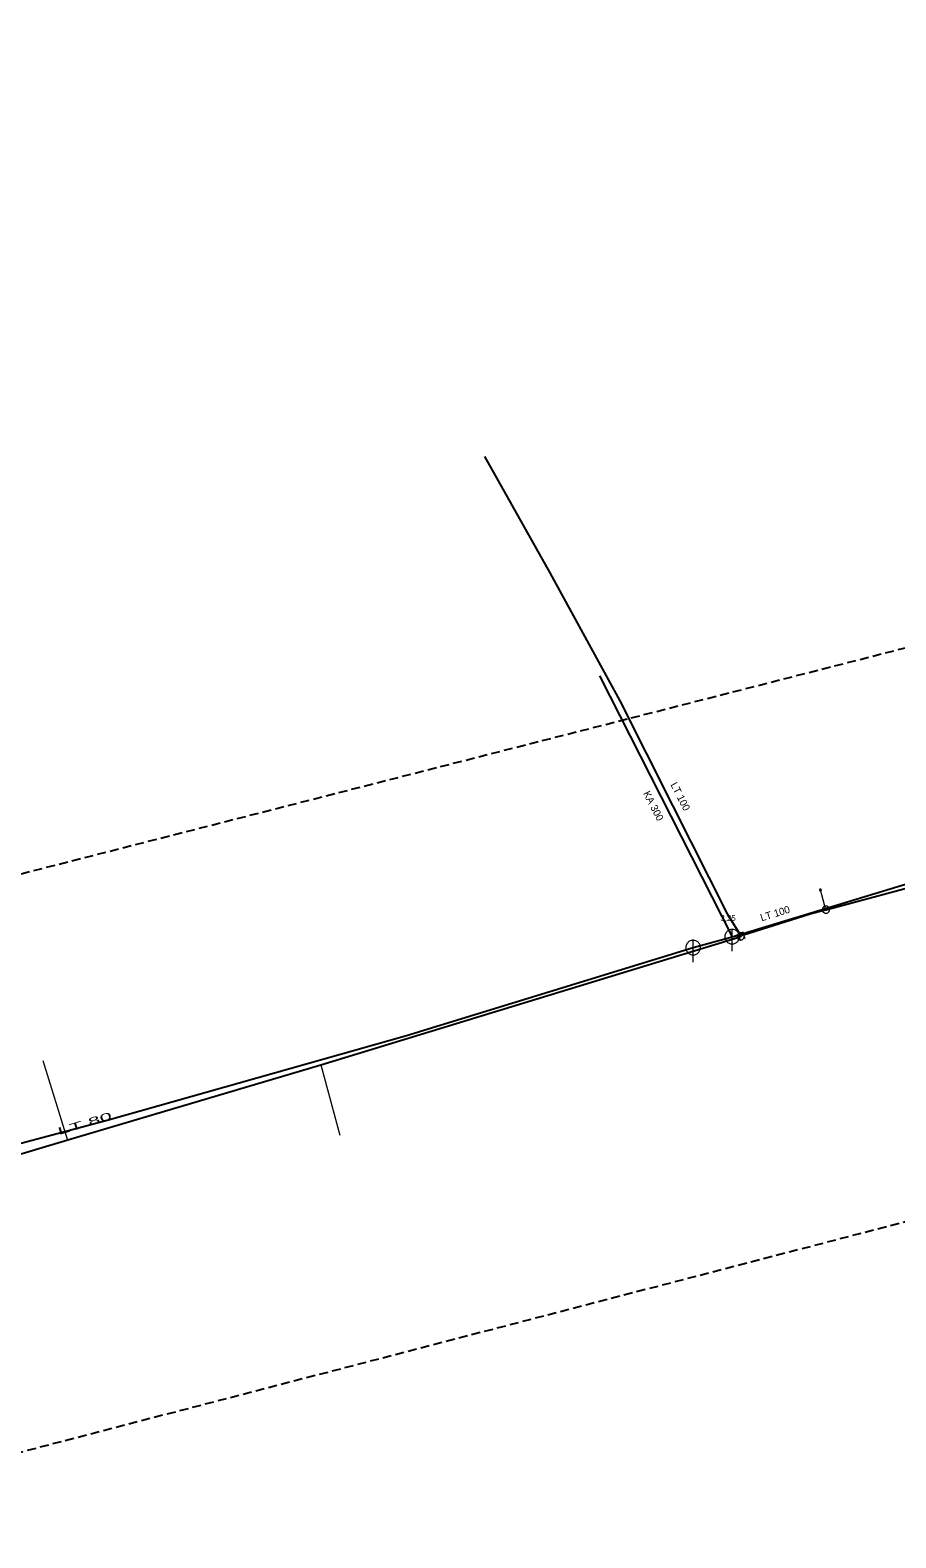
# Model space of a CAD drawing. Extents: x -690254 to -689100, y -975264 to -974703.
# Drawn here: x -689579.1 to -689460.4, y -974970.5 to -974763.7 of the extents above; entities that cross this region are included whole.
import ezdxf

# ---------------------------------------------------------------- set-up
doc = ezdxf.new("R2010")
doc.units = 0
doc.header["$LTSCALE"] = 0.4
doc.linetypes.add('MEDIUM_DASHED', pattern=[4.5, 3, -1.5])
for name, color, linetype, lineweight in [('1', 7, 'Continuous', 13), ('13', 7, 'Continuous', 13), ('14', 7, 'Continuous', 13), ('17', 7, 'Continuous', 25), ('22', 7, 'Continuous', 13), ('34', 7, 'Continuous', 13), ('47', 7, 'Continuous', 13), ('63', 7, 'MEDIUM_DASHED', 25), ('9', 7, 'Continuous', 13)]:
    doc.layers.add(name, color=color, linetype=linetype, lineweight=lineweight)

msp = doc.modelspace()

# ---------------------------------------------------------------- linework, layer by layer
at = {"layer": '13'}
for p, q in [((-689573.992, -974915.884), (-689577.329, -974905.072)), ((-689539.272, -974905.616), (-689536.647, -974915.287))]:
    msp.add_line(p, q, dxfattribs=at)
at = {"layer": '14', "lineweight": 25}
msp.add_line((-689501.039, -974852.239), (-689482.829, -974888.039), dxfattribs=at)
at = {"layer": '14'}
for p, q in [((-689469.955, -974884.335), (-689470.711, -974881.63)), ((-689573.976, -974915.931), (-689573.992, -974915.884))]:
    msp.add_line(p, q, dxfattribs=at)
at = {"layer": '14', "lineweight": 25}
for points in [[(-689488.181, -974889.533), (-689482.829, -974888.039), (-689415.219, -974867.53)], [(-689624.679, -974928.186), (-689568.576, -974913.204), (-689527.509, -974901.581), (-689488.181, -974889.533)]]:
    msp.add_lwpolyline(points, dxfattribs=at)
at = {"layer": '14'}
msp.add_lwpolyline([(-689481.914, -974888.101), (-689481.66, -974888), (-689481.25, -974887.809)], dxfattribs=at)
at = {"layer": '17'}
for points in [[(-689516.78, -974822.14), (-689507.85, -974838.14), (-689498.219, -974855.68), (-689491, -974870.039), (-689483.487, -974884.918), (-689481.92, -974887.48), (-689481.66, -974888)], [(-689469.955, -974884.335), (-689442.62, -974876.987), (-689427.163, -974872.924), (-689420.942, -974870.852), (-689400.344, -974864.98), (-689376.509, -974858.111), (-689369.914, -974856.032), (-689358.632, -974852.602)], [(-689481.25, -974887.809), (-689472.099, -974884.916), (-689469.955, -974884.335)], [(-689605.756, -974925.377), (-689599.249, -974923.443), (-689573.976, -974915.931), (-689539.272, -974905.616), (-689481.914, -974888.101)]]:
    msp.add_lwpolyline(points, dxfattribs=at)
at = {"layer": '22'}
for p, q in [((-689482.829, -974890.039), (-689482.828, -974887.039)), ((-689488.181, -974891.533), (-689488.18, -974888.533))]:
    msp.add_line(p, q, dxfattribs=at)
for points in [[(-689481.829, -974888.039), (-689481.834, -974887.93), (-689481.852, -974887.822), (-689481.882, -974887.716), (-689481.922, -974887.615), (-689481.974, -974887.518), (-689482.036, -974887.428), (-689482.108, -974887.345), (-689482.188, -974887.271), (-689482.276, -974887.205), (-689482.37, -974887.15), (-689482.47, -974887.105), (-689482.575, -974887.072), (-689482.682, -974887.05), (-689482.791, -974887.04), (-689482.901, -974887.042), (-689483.009, -974887.056), (-689483.116, -974887.081), (-689483.219, -974887.118), (-689483.317, -974887.167), (-689483.409, -974887.225), (-689483.495, -974887.294), (-689483.572, -974887.371), (-689483.641, -974887.457), (-689483.7, -974887.549), (-689483.748, -974887.647), (-689483.785, -974887.75), (-689483.811, -974887.857), (-689483.825, -974887.965), (-689483.828, -974888.075), (-689483.818, -974888.184), (-689483.797, -974888.291), (-689483.763, -974888.395), (-689483.719, -974888.495), (-689483.664, -974888.59), (-689483.598, -974888.678), (-689483.524, -974888.758), (-689483.441, -974888.83), (-689483.351, -974888.892), (-689483.255, -974888.944), (-689483.153, -974888.985), (-689483.048, -974889.015), (-689482.94, -974889.033), (-689482.83, -974889.039), (-689482.721, -974889.033), (-689482.613, -974889.015), (-689482.508, -974888.986), (-689482.406, -974888.945), (-689482.309, -974888.893), (-689482.219, -974888.831), (-689482.136, -974888.76), (-689482.061, -974888.68), (-689481.996, -974888.592), (-689481.94, -974888.498), (-689481.896, -974888.398), (-689481.862, -974888.294), (-689481.84, -974888.186), (-689481.83, -974888.077)], [(-689487.181, -974889.533), (-689487.186, -974889.424), (-689487.204, -974889.316), (-689487.234, -974889.21), (-689487.274, -974889.109), (-689487.326, -974889.012), (-689487.388, -974888.922), (-689487.46, -974888.839), (-689487.54, -974888.765), (-689487.628, -974888.699), (-689487.722, -974888.644), (-689487.822, -974888.599), (-689487.927, -974888.566), (-689488.034, -974888.544), (-689488.143, -974888.534), (-689488.253, -974888.536), (-689488.361, -974888.55), (-689488.468, -974888.575), (-689488.571, -974888.612), (-689488.669, -974888.661), (-689488.761, -974888.719), (-689488.847, -974888.788), (-689488.924, -974888.865), (-689488.993, -974888.951), (-689489.052, -974889.043), (-689489.1, -974889.141), (-689489.137, -974889.244), (-689489.163, -974889.351), (-689489.177, -974889.459), (-689489.18, -974889.569), (-689489.17, -974889.678), (-689489.149, -974889.785), (-689489.115, -974889.889), (-689489.071, -974889.989), (-689489.016, -974890.084), (-689488.95, -974890.172), (-689488.876, -974890.252), (-689488.793, -974890.324), (-689488.703, -974890.386), (-689488.607, -974890.438), (-689488.505, -974890.479), (-689488.4, -974890.509), (-689488.292, -974890.527), (-689488.182, -974890.533), (-689488.073, -974890.527), (-689487.965, -974890.509), (-689487.86, -974890.48), (-689487.758, -974890.439), (-689487.661, -974890.387), (-689487.571, -974890.325), (-689487.488, -974890.254), (-689487.413, -974890.174), (-689487.348, -974890.086), (-689487.292, -974889.992), (-689487.248, -974889.892), (-689487.214, -974889.788), (-689487.192, -974889.68), (-689487.182, -974889.571)]]:
    msp.add_lwpolyline(points, close=True, dxfattribs=at)
at = {"layer": '34'}
for p, q in [((-689481.401, -974887.332), (-689481.099, -974888.285)), ((-689482.156, -974887.663), (-689481.672, -974888.538)), ((-689574.465, -974916.045), (-689573.518, -974915.723))]:
    msp.add_line(p, q, dxfattribs=at)
at = {"layer": '47'}
for points in [[(-689469.474, -974884.197), (-689469.491, -974884.148), (-689469.513, -974884.1), (-689469.54, -974884.056), (-689469.571, -974884.014), (-689469.607, -974883.975), (-689469.647, -974883.941), (-689469.689, -974883.911), (-689469.735, -974883.886), (-689469.783, -974883.865), (-689469.833, -974883.849), (-689469.885, -974883.839), (-689469.937, -974883.835), (-689469.989, -974883.836), (-689470.041, -974883.842), (-689470.092, -974883.854), (-689470.141, -974883.871), (-689470.189, -974883.893), (-689470.234, -974883.92), (-689470.275, -974883.951), (-689470.314, -974883.987), (-689470.348, -974884.027), (-689470.378, -974884.07), (-689470.404, -974884.115), (-689470.425, -974884.163), (-689470.44, -974884.213), (-689470.45, -974884.265), (-689470.454, -974884.317), (-689470.453, -974884.369), (-689470.447, -974884.421), (-689470.435, -974884.472), (-689470.418, -974884.521), (-689470.396, -974884.569), (-689470.37, -974884.614), (-689470.338, -974884.655), (-689470.302, -974884.694), (-689470.263, -974884.728), (-689470.22, -974884.759), (-689470.174, -974884.784), (-689470.126, -974884.805), (-689470.076, -974884.82), (-689470.024, -974884.83), (-689469.973, -974884.835), (-689469.92, -974884.833), (-689469.868, -974884.827), (-689469.817, -974884.815), (-689469.768, -974884.798), (-689469.72, -974884.776), (-689469.676, -974884.75), (-689469.634, -974884.718), (-689469.595, -974884.682), (-689469.561, -974884.643), (-689469.531, -974884.6), (-689469.506, -974884.555), (-689469.485, -974884.506), (-689469.469, -974884.456), (-689469.459, -974884.404), (-689469.455, -974884.353), (-689469.456, -974884.3), (-689469.462, -974884.248)], [(-689469.876, -974884.312), (-689469.878, -974884.303), (-689469.882, -974884.296), (-689469.886, -974884.289), (-689469.891, -974884.282), (-689469.897, -974884.276), (-689469.904, -974884.27), (-689469.911, -974884.265), (-689469.918, -974884.261), (-689469.926, -974884.258), (-689469.935, -974884.255), (-689469.943, -974884.253), (-689469.952, -974884.253), (-689469.96, -974884.253), (-689469.968, -974884.253), (-689469.977, -974884.256), (-689469.986, -974884.258), (-689469.993, -974884.262), (-689470, -974884.266), (-689470.007, -974884.271), (-689470.013, -974884.277), (-689470.019, -974884.284), (-689470.024, -974884.291), (-689470.028, -974884.298), (-689470.032, -974884.307), (-689470.034, -974884.315), (-689470.036, -974884.323), (-689470.036, -974884.332), (-689470.036, -974884.34), (-689470.036, -974884.348), (-689470.033, -974884.357), (-689470.031, -974884.366), (-689470.027, -974884.373), (-689470.023, -974884.38), (-689470.018, -974884.387), (-689470.012, -974884.393), (-689470.006, -974884.399), (-689469.998, -974884.404), (-689469.991, -974884.408), (-689469.982, -974884.412), (-689469.974, -974884.414), (-689469.966, -974884.416), (-689469.957, -974884.416), (-689469.949, -974884.416), (-689469.941, -974884.416), (-689469.932, -974884.413), (-689469.923, -974884.411), (-689469.916, -974884.407), (-689469.909, -974884.403), (-689469.902, -974884.398), (-689469.896, -974884.392), (-689469.89, -974884.386), (-689469.885, -974884.378), (-689469.881, -974884.371), (-689469.878, -974884.363), (-689469.875, -974884.354), (-689469.873, -974884.346), (-689469.873, -974884.337), (-689469.873, -974884.329), (-689469.873, -974884.321)], [(-689481.178, -974887.863), (-689481.196, -974887.814), (-689481.217, -974887.766), (-689481.245, -974887.722), (-689481.275, -974887.679), (-689481.311, -974887.641), (-689481.351, -974887.606), (-689481.394, -974887.577), (-689481.439, -974887.551), (-689481.487, -974887.531), (-689481.537, -974887.515), (-689481.589, -974887.504), (-689481.641, -974887.501), (-689481.693, -974887.501), (-689481.745, -974887.507), (-689481.796, -974887.518), (-689481.845, -974887.536), (-689481.893, -974887.557), (-689481.938, -974887.585), (-689481.98, -974887.615), (-689482.018, -974887.651), (-689482.053, -974887.691), (-689482.083, -974887.734), (-689482.109, -974887.78), (-689482.129, -974887.827), (-689482.144, -974887.877), (-689482.155, -974887.929), (-689482.159, -974887.981), (-689482.158, -974888.033), (-689482.152, -974888.085), (-689482.141, -974888.136), (-689482.123, -974888.185), (-689482.102, -974888.233), (-689482.075, -974888.279), (-689482.044, -974888.32), (-689482.008, -974888.358), (-689481.969, -974888.393), (-689481.926, -974888.423), (-689481.88, -974888.449), (-689481.832, -974888.469), (-689481.782, -974888.484), (-689481.73, -974888.495), (-689481.679, -974888.5), (-689481.626, -974888.498), (-689481.574, -974888.492), (-689481.523, -974888.481), (-689481.474, -974888.463), (-689481.426, -974888.442), (-689481.381, -974888.415), (-689481.339, -974888.384), (-689481.301, -974888.348), (-689481.266, -974888.309), (-689481.237, -974888.266), (-689481.211, -974888.221), (-689481.191, -974888.172), (-689481.175, -974888.122), (-689481.164, -974888.07), (-689481.16, -974888.019), (-689481.161, -974887.966), (-689481.167, -974887.914)], [(-689481.581, -974887.977), (-689481.583, -974887.968), (-689481.587, -974887.961), (-689481.591, -974887.954), (-689481.596, -974887.947), (-689481.602, -974887.941), (-689481.609, -974887.935), (-689481.616, -974887.93), (-689481.623, -974887.926), (-689481.631, -974887.923), (-689481.639, -974887.92), (-689481.648, -974887.918), (-689481.657, -974887.918), (-689481.665, -974887.918), (-689481.673, -974887.918), (-689481.682, -974887.921), (-689481.691, -974887.923), (-689481.698, -974887.927), (-689481.705, -974887.931), (-689481.712, -974887.936), (-689481.718, -974887.942), (-689481.724, -974887.949), (-689481.729, -974887.956), (-689481.733, -974887.963), (-689481.737, -974887.972), (-689481.739, -974887.979), (-689481.741, -974887.988), (-689481.741, -974887.997), (-689481.741, -974888.005), (-689481.741, -974888.013), (-689481.738, -974888.022), (-689481.736, -974888.031), (-689481.732, -974888.038), (-689481.728, -974888.045), (-689481.723, -974888.052), (-689481.717, -974888.058), (-689481.711, -974888.064), (-689481.703, -974888.069), (-689481.696, -974888.073), (-689481.687, -974888.077), (-689481.68, -974888.079), (-689481.671, -974888.081), (-689481.662, -974888.081), (-689481.654, -974888.081), (-689481.646, -974888.081), (-689481.637, -974888.078), (-689481.628, -974888.076), (-689481.621, -974888.072), (-689481.614, -974888.068), (-689481.607, -974888.063), (-689481.601, -974888.057), (-689481.595, -974888.051), (-689481.59, -974888.043), (-689481.586, -974888.036), (-689481.583, -974888.028), (-689481.58, -974888.02), (-689481.578, -974888.011), (-689481.578, -974888.002), (-689481.578, -974887.994), (-689481.578, -974887.986)]]:
    msp.add_lwpolyline(points, close=True, dxfattribs=at)
at = {"layer": '63'}
msp.add_lwpolyline([(-690175.832, -975238.167), (-690201.511, -975156.663), (-690201.511, -975156.663), (-689696.859, -975008.171), (-689696.859, -975008.171), (-689730.354, -974917.735), (-689730.354, -974917.735), (-689127.452, -974763.66), (-689127.452, -974763.66), (-689118.52, -974838.465), (-689118.52, -974838.465), (-689624.288, -974970.21), (-689624.288, -974970.21), (-689593.026, -975070.694), (-689593.026, -975070.694)], close=True, dxfattribs=at)
at = {"layer": '9'}
for points in [[(-689470.837, -974881.63), (-689470.837, -974881.643), (-689470.835, -974881.656), (-689470.832, -974881.669), (-689470.827, -974881.681), (-689470.821, -974881.693), (-689470.814, -974881.704), (-689470.806, -974881.714), (-689470.796, -974881.724), (-689470.786, -974881.732), (-689470.775, -974881.739), (-689470.763, -974881.745), (-689470.751, -974881.75), (-689470.738, -974881.753), (-689470.725, -974881.755), (-689470.712, -974881.757), (-689470.699, -974881.756), (-689470.686, -974881.754), (-689470.673, -974881.751), (-689470.661, -974881.746), (-689470.649, -974881.74), (-689470.638, -974881.733), (-689470.628, -974881.725), (-689470.618, -974881.715), (-689470.61, -974881.705), (-689470.603, -974881.694), (-689470.597, -974881.682), (-689470.592, -974881.67), (-689470.589, -974881.657), (-689470.587, -974881.644), (-689470.585, -974881.631), (-689470.586, -974881.618), (-689470.588, -974881.605), (-689470.591, -974881.592), (-689470.596, -974881.58), (-689470.602, -974881.568), (-689470.609, -974881.557), (-689470.617, -974881.547), (-689470.627, -974881.537), (-689470.637, -974881.529), (-689470.648, -974881.522), (-689470.66, -974881.516), (-689470.672, -974881.511), (-689470.685, -974881.508), (-689470.698, -974881.506), (-689470.711, -974881.505), (-689470.724, -974881.505), (-689470.737, -974881.507), (-689470.75, -974881.51), (-689470.762, -974881.515), (-689470.774, -974881.521), (-689470.785, -974881.528), (-689470.795, -974881.536), (-689470.805, -974881.546), (-689470.813, -974881.556), (-689470.82, -974881.567), (-689470.826, -974881.579), (-689470.831, -974881.591), (-689470.834, -974881.604), (-689470.836, -974881.617)], [(-689470.817, -974881.63), (-689470.818, -974881.641), (-689470.816, -974881.652), (-689470.813, -974881.663), (-689470.809, -974881.673), (-689470.804, -974881.683), (-689470.798, -974881.692), (-689470.791, -974881.701), (-689470.783, -974881.709), (-689470.774, -974881.716), (-689470.765, -974881.722), (-689470.755, -974881.727), (-689470.745, -974881.731), (-689470.734, -974881.734), (-689470.723, -974881.737), (-689470.712, -974881.737), (-689470.701, -974881.737), (-689470.69, -974881.735), (-689470.679, -974881.732), (-689470.669, -974881.728), (-689470.659, -974881.723), (-689470.65, -974881.717), (-689470.641, -974881.71), (-689470.633, -974881.702), (-689470.626, -974881.693), (-689470.62, -974881.684), (-689470.615, -974881.674), (-689470.611, -974881.664), (-689470.608, -974881.653), (-689470.606, -974881.642), (-689470.605, -974881.631), (-689470.605, -974881.62), (-689470.607, -974881.609), (-689470.61, -974881.598), (-689470.614, -974881.588), (-689470.619, -974881.578), (-689470.625, -974881.569), (-689470.632, -974881.56), (-689470.64, -974881.552), (-689470.649, -974881.545), (-689470.658, -974881.539), (-689470.668, -974881.534), (-689470.678, -974881.53), (-689470.689, -974881.527), (-689470.7, -974881.525), (-689470.711, -974881.525), (-689470.722, -974881.524), (-689470.733, -974881.526), (-689470.744, -974881.529), (-689470.754, -974881.533), (-689470.764, -974881.538), (-689470.773, -974881.544), (-689470.782, -974881.551), (-689470.79, -974881.559), (-689470.797, -974881.568), (-689470.803, -974881.577), (-689470.808, -974881.587), (-689470.812, -974881.597), (-689470.815, -974881.608), (-689470.817, -974881.619)], [(-689470.798, -974881.63), (-689470.798, -974881.639), (-689470.797, -974881.648), (-689470.794, -974881.657), (-689470.791, -974881.665), (-689470.787, -974881.673), (-689470.782, -974881.681), (-689470.776, -974881.688), (-689470.77, -974881.694), (-689470.763, -974881.7), (-689470.755, -974881.705), (-689470.747, -974881.709), (-689470.739, -974881.712), (-689470.73, -974881.715), (-689470.721, -974881.716), (-689470.712, -974881.718), (-689470.703, -974881.717), (-689470.694, -974881.716), (-689470.685, -974881.713), (-689470.677, -974881.71), (-689470.669, -974881.706), (-689470.661, -974881.701), (-689470.654, -974881.695), (-689470.648, -974881.689), (-689470.642, -974881.682), (-689470.637, -974881.674), (-689470.633, -974881.666), (-689470.63, -974881.658), (-689470.627, -974881.649), (-689470.626, -974881.64), (-689470.624, -974881.631), (-689470.625, -974881.622), (-689470.626, -974881.613), (-689470.629, -974881.604), (-689470.632, -974881.596), (-689470.636, -974881.588), (-689470.641, -974881.58), (-689470.647, -974881.573), (-689470.653, -974881.567), (-689470.66, -974881.561), (-689470.668, -974881.556), (-689470.676, -974881.552), (-689470.684, -974881.549), (-689470.693, -974881.546), (-689470.702, -974881.545), (-689470.711, -974881.544), (-689470.72, -974881.544), (-689470.729, -974881.545), (-689470.738, -974881.548), (-689470.746, -974881.551), (-689470.754, -974881.555), (-689470.762, -974881.56), (-689470.769, -974881.566), (-689470.775, -974881.572), (-689470.781, -974881.579), (-689470.786, -974881.587), (-689470.79, -974881.595), (-689470.793, -974881.603), (-689470.796, -974881.612), (-689470.797, -974881.621)], [(-689470.778, -974881.63), (-689470.778, -974881.637), (-689470.777, -974881.644), (-689470.776, -974881.651), (-689470.773, -974881.657), (-689470.77, -974881.663), (-689470.766, -974881.669), (-689470.762, -974881.675), (-689470.757, -974881.68), (-689470.751, -974881.684), (-689470.745, -974881.688), (-689470.739, -974881.691), (-689470.733, -974881.694), (-689470.726, -974881.695), (-689470.719, -974881.698), (-689470.712, -974881.698), (-689470.705, -974881.698), (-689470.698, -974881.696), (-689470.691, -974881.695), (-689470.685, -974881.692), (-689470.678, -974881.689), (-689470.673, -974881.685), (-689470.667, -974881.681), (-689470.662, -974881.676), (-689470.658, -974881.67), (-689470.654, -974881.664), (-689470.651, -974881.658), (-689470.648, -974881.652), (-689470.646, -974881.645), (-689470.645, -974881.638), (-689470.644, -974881.631), (-689470.644, -974881.624), (-689470.645, -974881.617), (-689470.647, -974881.61), (-689470.65, -974881.604), (-689470.653, -974881.597), (-689470.657, -974881.592), (-689470.661, -974881.586), (-689470.666, -974881.581), (-689470.672, -974881.577), (-689470.677, -974881.573), (-689470.684, -974881.57), (-689470.69, -974881.567), (-689470.697, -974881.565), (-689470.704, -974881.564), (-689470.711, -974881.564), (-689470.718, -974881.564), (-689470.725, -974881.564), (-689470.732, -974881.566), (-689470.738, -974881.569), (-689470.744, -974881.572), (-689470.75, -974881.576), (-689470.756, -974881.58), (-689470.761, -974881.585), (-689470.765, -974881.591), (-689470.769, -974881.596), (-689470.772, -974881.603), (-689470.775, -974881.609), (-689470.776, -974881.616), (-689470.778, -974881.623)], [(-689470.758, -974881.63), (-689470.758, -974881.635), (-689470.758, -974881.64), (-689470.757, -974881.645), (-689470.755, -974881.649), (-689470.753, -974881.654), (-689470.75, -974881.658), (-689470.747, -974881.661), (-689470.743, -974881.665), (-689470.74, -974881.668), (-689470.736, -974881.671), (-689470.731, -974881.673), (-689470.727, -974881.675), (-689470.722, -974881.676), (-689470.717, -974881.678), (-689470.712, -974881.678), (-689470.707, -974881.678), (-689470.702, -974881.677), (-689470.697, -974881.676), (-689470.693, -974881.674), (-689470.688, -974881.672), (-689470.684, -974881.669), (-689470.68, -974881.666), (-689470.677, -974881.662), (-689470.674, -974881.659), (-689470.671, -974881.655), (-689470.669, -974881.65), (-689470.667, -974881.646), (-689470.666, -974881.641), (-689470.665, -974881.636), (-689470.664, -974881.631), (-689470.664, -974881.626), (-689470.665, -974881.621), (-689470.666, -974881.616), (-689470.668, -974881.612), (-689470.67, -974881.607), (-689470.673, -974881.603), (-689470.676, -974881.599), (-689470.679, -974881.596), (-689470.683, -974881.593), (-689470.687, -974881.59), (-689470.692, -974881.588), (-689470.696, -974881.586), (-689470.701, -974881.585), (-689470.706, -974881.584), (-689470.711, -974881.584), (-689470.716, -974881.584), (-689470.721, -974881.585), (-689470.726, -974881.585), (-689470.73, -974881.587), (-689470.735, -974881.589), (-689470.739, -974881.592), (-689470.742, -974881.595), (-689470.746, -974881.598), (-689470.749, -974881.602), (-689470.752, -974881.606), (-689470.754, -974881.611), (-689470.756, -974881.615), (-689470.757, -974881.62), (-689470.758, -974881.625)], [(-689470.738, -974881.63), (-689470.738, -974881.633), (-689470.739, -974881.636), (-689470.738, -974881.638), (-689470.737, -974881.641), (-689470.736, -974881.644), (-689470.734, -974881.646), (-689470.732, -974881.648), (-689470.73, -974881.65), (-689470.728, -974881.652), (-689470.726, -974881.654), (-689470.723, -974881.656), (-689470.72, -974881.657), (-689470.718, -974881.657), (-689470.715, -974881.658), (-689470.712, -974881.658), (-689470.709, -974881.658), (-689470.706, -974881.658), (-689470.703, -974881.657), (-689470.701, -974881.656), (-689470.698, -974881.655), (-689470.696, -974881.653), (-689470.693, -974881.651), (-689470.691, -974881.649), (-689470.69, -974881.647), (-689470.688, -974881.645), (-689470.687, -974881.642), (-689470.685, -974881.639), (-689470.685, -974881.637), (-689470.684, -974881.634), (-689470.683, -974881.631), (-689470.684, -974881.628), (-689470.684, -974881.625), (-689470.685, -974881.622), (-689470.686, -974881.62), (-689470.687, -974881.617), (-689470.689, -974881.615), (-689470.69, -974881.612), (-689470.692, -974881.61), (-689470.695, -974881.609), (-689470.697, -974881.607), (-689470.7, -974881.606), (-689470.702, -974881.605), (-689470.705, -974881.604), (-689470.708, -974881.604), (-689470.711, -974881.603), (-689470.714, -974881.604), (-689470.717, -974881.603), (-689470.719, -974881.605), (-689470.722, -974881.605), (-689470.725, -974881.606), (-689470.727, -974881.608), (-689470.729, -974881.609), (-689470.731, -974881.611), (-689470.733, -974881.614), (-689470.735, -974881.616), (-689470.736, -974881.619), (-689470.737, -974881.621), (-689470.738, -974881.624), (-689470.738, -974881.627)], [(-689470.719, -974881.63), (-689470.719, -974881.632), (-689470.719, -974881.632), (-689470.718, -974881.632), (-689470.718, -974881.634), (-689470.719, -974881.635), (-689470.717, -974881.635), (-689470.717, -974881.635), (-689470.717, -974881.637), (-689470.717, -974881.637), (-689470.716, -974881.638), (-689470.714, -974881.638), (-689470.714, -974881.638), (-689470.714, -974881.639), (-689470.712, -974881.639), (-689470.712, -974881.639), (-689470.711, -974881.639), (-689470.71, -974881.639), (-689470.71, -974881.638), (-689470.709, -974881.638), (-689470.707, -974881.638), (-689470.707, -974881.637), (-689470.707, -974881.637), (-689470.706, -974881.636), (-689470.706, -974881.636), (-689470.704, -974881.635), (-689470.704, -974881.634), (-689470.703, -974881.633), (-689470.703, -974881.633), (-689470.703, -974881.632), (-689470.703, -974881.631), (-689470.703, -974881.63), (-689470.703, -974881.629), (-689470.703, -974881.629), (-689470.704, -974881.628), (-689470.704, -974881.627), (-689470.705, -974881.626), (-689470.705, -974881.626), (-689470.706, -974881.625), (-689470.706, -974881.625), (-689470.707, -974881.624), (-689470.708, -974881.624), (-689470.709, -974881.623), (-689470.709, -974881.623), (-689470.71, -974881.623), (-689470.711, -974881.623), (-689470.712, -974881.623), (-689470.713, -974881.623), (-689470.713, -974881.623), (-689470.714, -974881.624), (-689470.715, -974881.623), (-689470.716, -974881.625), (-689470.716, -974881.625), (-689470.717, -974881.625), (-689470.717, -974881.625), (-689470.718, -974881.627), (-689470.718, -974881.628), (-689470.718, -974881.629), (-689470.719, -974881.629), (-689470.719, -974881.63)]]:
    msp.add_lwpolyline(points, close=True, dxfattribs=at)

# ---------------------------------------------------------------- texts
at = {"layer": '1'}
for s, rotation, p in [('KA 300', 297, (-689495.063, -974868.365)), ('LT 100', 297, (-689491.323, -974867.175)), ('LT 100', 17, (-689478.781, -974885.94))]:
    msp.add_text(s, height=1, rotation=rotation, dxfattribs=at).set_placement(p)
msp.add_text('3,25', height=0.8, dxfattribs=at).set_placement((-689484.43, -974885.887))
at = {"layer": '1', "width": 2.25}
msp.add_text('LT 80 ', height=1, rotation=17, dxfattribs=at).set_placement((-689575.19, -974915.264))

doc.saveas('drawing.dxf')
